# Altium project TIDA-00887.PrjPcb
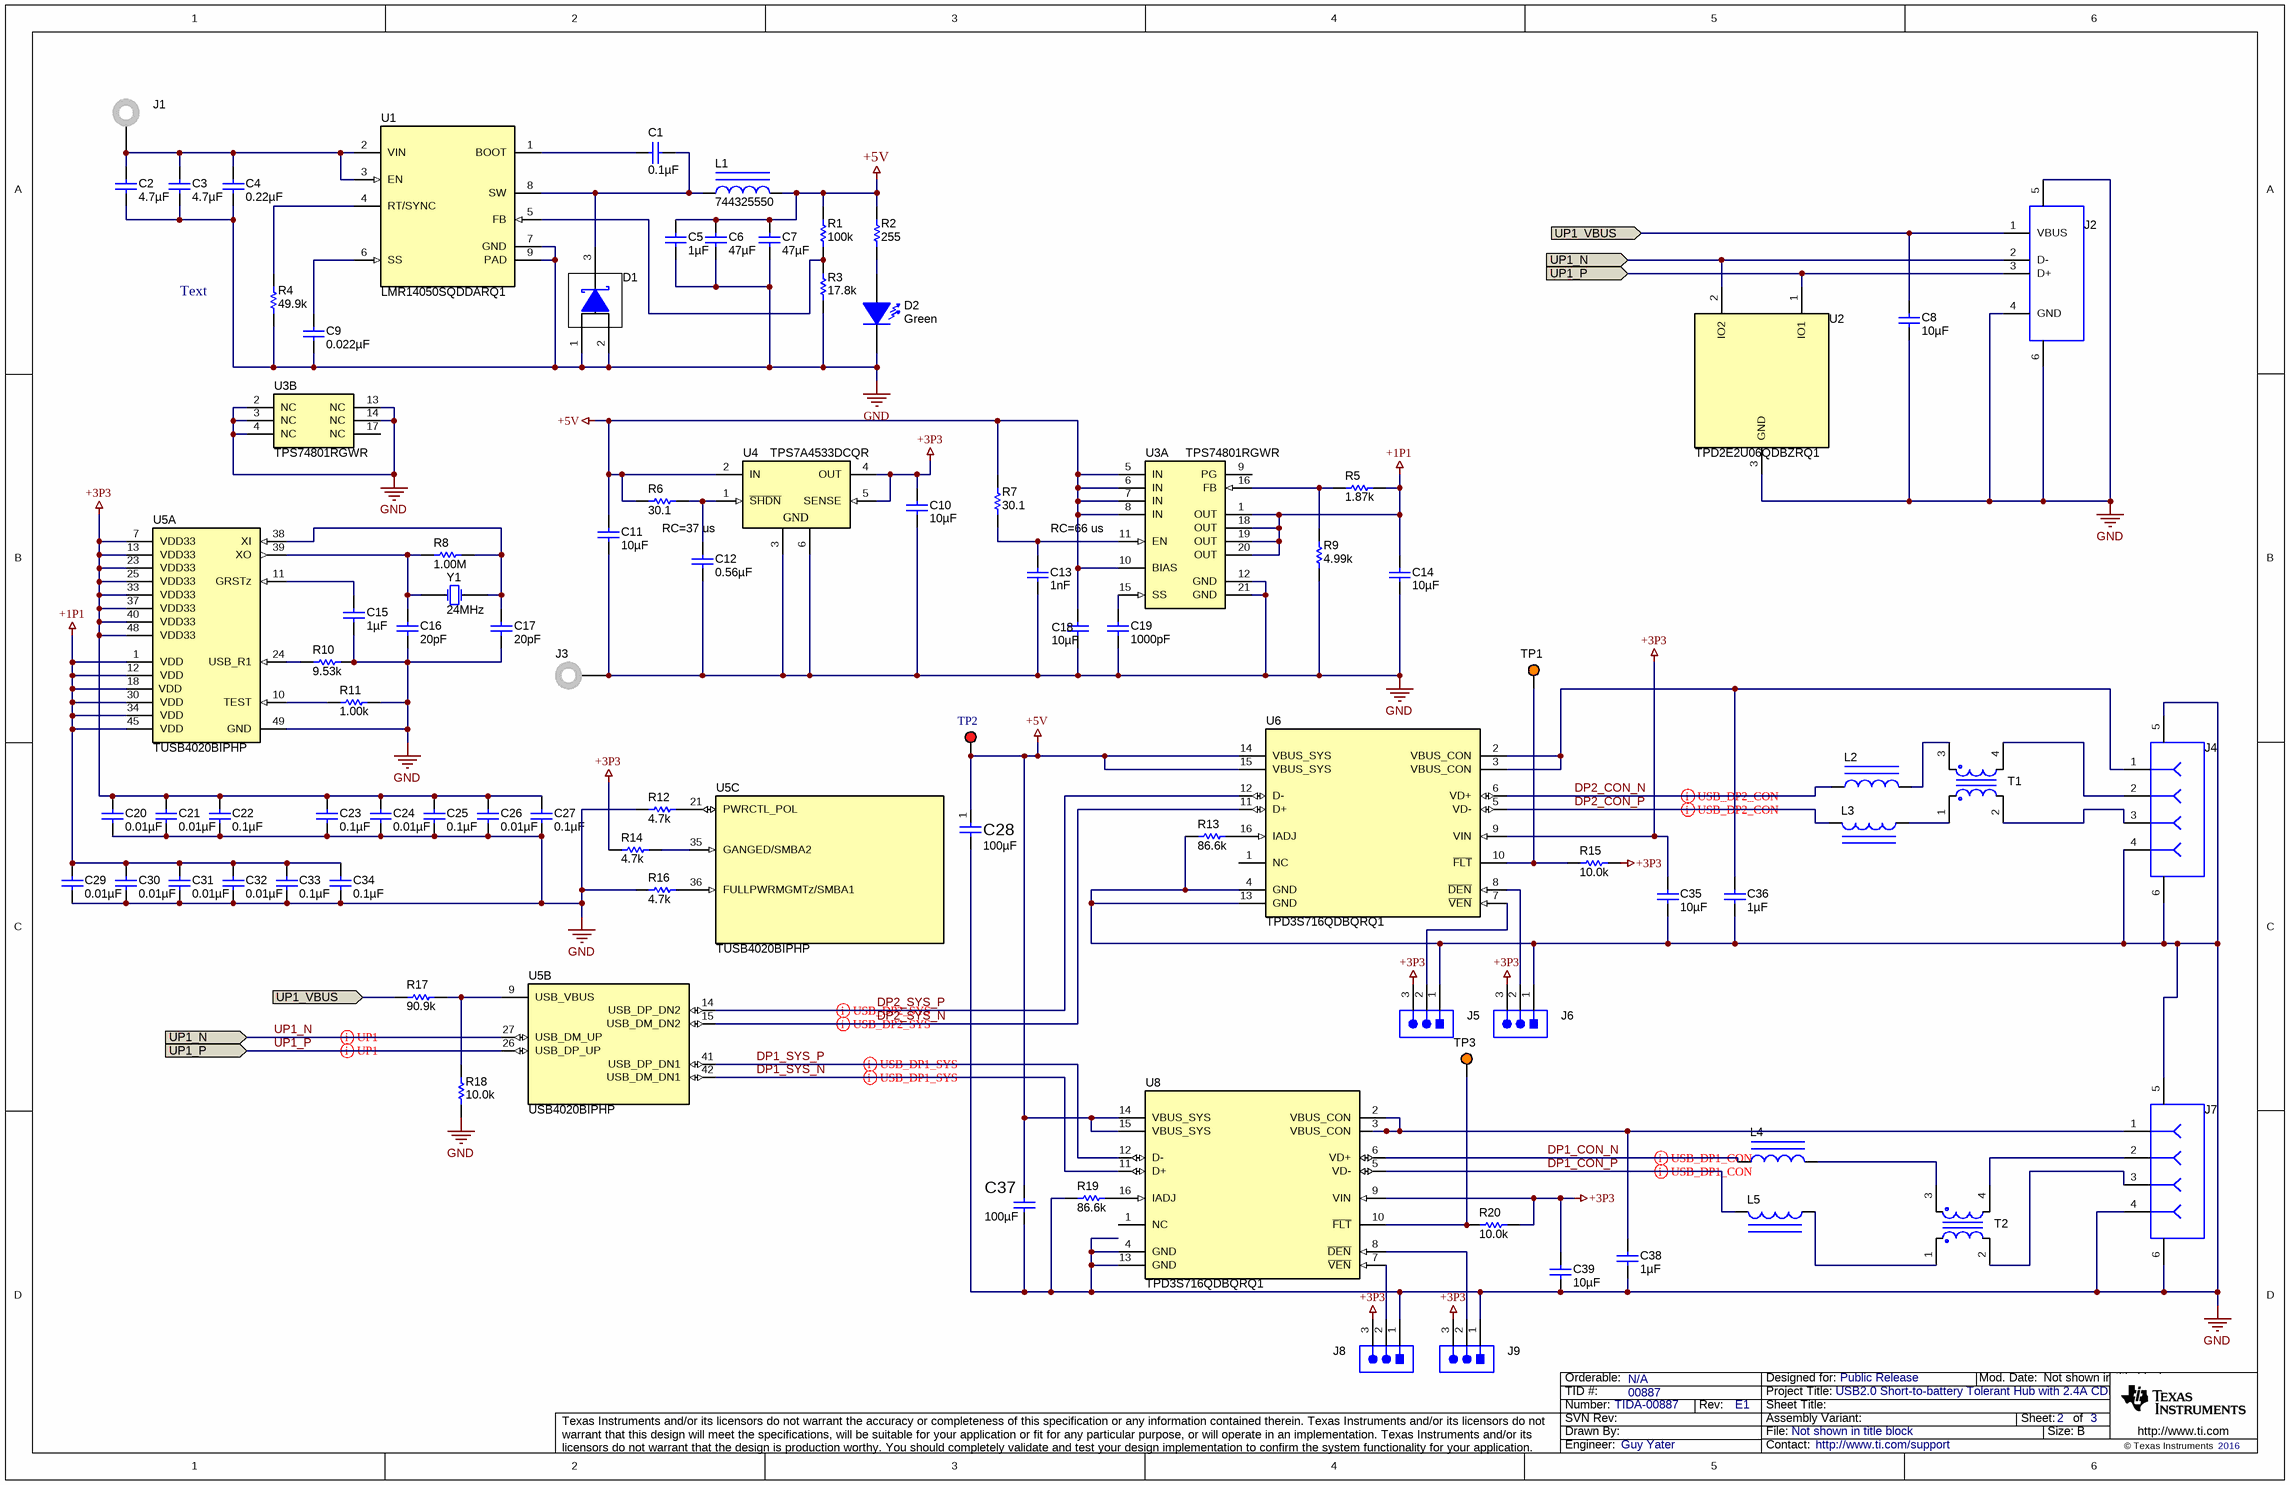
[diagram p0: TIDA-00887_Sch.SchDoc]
TID: 00887; TechSupport: http://www.ti.com/support; SCH_Rev: E1; PRJ_Title: USB2.0 Short-to-battery Tolerant Hub with 2.4A CDP + DCP support; PRJ_Number: TIDA-00887; PRJ_Engineer: Guy Yater; PRJ_Customer: Public Release; PCB_Rev: E1; PCB_Layout: Guy Yater; EVM_Orderable: N/A; CopyrightYear: 2016
2 sheets, 97 parts. Net scope: flat (ports and power ports of the same name join across sheets).
Board file: TIDA-00887_PCB.PcbDoc
Sheets:
  TIDA-00887_Sch.SchDoc
  TIDA-00887_Hardware.SchDoc

## Sheet TIDA-00887_Sch.SchDoc
size 431 x 279 mm; Date: Not shown in title block; ApprovedBy: Not shown in title block; CheckedBy: Not shown in title block; Author: Not shown in title block; CompanyName: Not shown in title block; Engineer: Not shown in title block; Organization: Not shown in title block; Address1: Not shown in title block; Address2: Not shown in title block; Address3: Not shown in title block; Address4: Not shown in title block; DocumentNumber: 1; Revision: Use project parameter SCH_Rev; SheetNumber: 2; SheetTotal: 3; PageSetup: Record=PageOptions¦CenterHorizontal=True¦CenterVertical=True¦PrintScale=1.00¦XCorrection=1.00¦YCorrection=1.00¦PrintKind=0¦BorderSize=5000000¦LeftOffset=0¦BottomOffset=0¦Orientation=2¦PaperLength=1000¦PaperWidth=1000¦Scale=100¦PaperSource=15¦PrintQuality=600¦MediaType=1¦DitherType=10¦PaperKind=Letter¦PrintScaleMode=1

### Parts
C1  ValueDisplayed: 0.1µF  [0603]  (hidden comment: GRM188R71C104KA01D)
C2  ValueDisplayed: 4.7µF  [1210]  (hidden comment: GRM32ER71H475KA88L)
C3  ValueDisplayed: 4.7µF  [1210]  (hidden comment: GRM32ER71H475KA88L)
C4  ValueDisplayed: 0.22µF  [0805_HV]  (hidden comment: GRM21BR71H224KA01L)
C5  ValueDisplayed: 1µF  [0805_HV]  (hidden comment: GRM21BR71E105KA99L)
C6  ValueDisplayed: 47µF  [1210]  (hidden comment: GRM32ER61C476ME15L)
C7  ValueDisplayed: 47µF  [1210]  (hidden comment: GRM32ER61C476ME15L)
C8  ValueDisplayed: 10µF  [0805L]  (hidden comment: C2012X7R0J106M125AB)
C9  ValueDisplayed: 0.022µF  [0402]  (hidden comment: GRM155R71C223KA01D)
C10  ValueDisplayed: 10µF  [0805_HV]  (hidden comment: 0805YD106MAT2A)
C11  ValueDisplayed: 10µF  [0805_HV]  (hidden comment: 0805YD106MAT2A)
C12  ValueDisplayed: 0.56µF  [1206]  (hidden comment: 12063C564KAT2A)
C13  ValueDisplayed: 1nF  [1206_190]  (hidden comment: 202R18W102KV4E)
C14  ValueDisplayed: 10µF  [0805_HV]  (hidden comment: 0805YD106MAT2A)
C15  ValueDisplayed: 1µF  [0402]  (hidden comment: GRM155R70J105MA12D)
C16  ValueDisplayed: 20pF  [0402]  (hidden comment: GRM1555C1H200JA01D)
C17  ValueDisplayed: 20pF  [0402]  (hidden comment: GRM1555C1H200JA01D)
C18  ValueDisplayed: 10µF  [0805_HV]  (hidden comment: 0805YD106MAT2A)
C19  ValueDisplayed: 1000pF  [1206_190]  (hidden comment: 202R18W102KV4E)
C20  ValueDisplayed: 0.01µF  [0402]  (hidden comment: GRM155R71H103KA88D)
C21  ValueDisplayed: 0.01µF  [0402]  (hidden comment: GRM155R71H103KA88D)
C22  ValueDisplayed: 0.1µF  [0402]  (hidden comment: TMK105B7104MV-FR)
C23  ValueDisplayed: 0.1µF  [0402]  (hidden comment: TMK105B7104MV-FR)
C24  ValueDisplayed: 0.01µF  [0402]  (hidden comment: GRM155R71H103KA88D)
C25  ValueDisplayed: 0.1µF  [0402]  (hidden comment: TMK105B7104MV-FR)
C26  ValueDisplayed: 0.01µF  [0402]  (hidden comment: GRM155R71H103KA88D)
C27  ValueDisplayed: 0.1µF  [0402]  (hidden comment: TMK105B7104MV-FR)
C28  ValueDisplayed: 100µF  [1210_280]  (hidden comment: C1210C107M8PACTU)
C29  ValueDisplayed: 0.01µF  [0402]  (hidden comment: GRM155R71H103KA88D)
C30  ValueDisplayed: 0.01µF  [0402]  (hidden comment: GRM155R71H103KA88D)
C31  ValueDisplayed: 0.01µF  [0402]  (hidden comment: GRM155R71H103KA88D)
C32  ValueDisplayed: 0.01µF  [0402]  (hidden comment: GRM155R71H103KA88D)
C33  ValueDisplayed: 0.1µF  [0402]  (hidden comment: TMK105B7104MV-FR)
C34  ValueDisplayed: 0.1µF  [0402]  (hidden comment: TMK105B7104MV-FR)
C35  ValueDisplayed: 10µF  [0805L]  (hidden comment: C2012X7R0J106M125AB)
C36  ValueDisplayed: 1µF  [1206_190]  (hidden comment: GCM31CR72A105KA03)
C37  ValueDisplayed: 100µF  [1210_280]  (hidden comment: C1210C107M8PACTU)
C38  ValueDisplayed: 1µF  [1206_190]  (hidden comment: GCM31CR72A105KA03)
C39  ValueDisplayed: 10µF  [0805L]  (hidden comment: C2012X7R0J106M125AB)
D1  PDS560-13  [PowerDI5]  (value not drawn)
D2  value Green  [LED_LTST-C171]  (hidden comment: LTST-C171GKT)
J1  575-4  [Keystone_575-4]  (value not drawn)
J2  67068-8000  [MOLEX_67068-8000]  (value not drawn)
J3  575-4  [Keystone_575-4]  (value not drawn)
J4  292303-4  [CONN_TE_292303-4]  (value not drawn)
J5  PEC03SAAN  [CONN_PEC03SAAN]  (value not drawn)
J6  PEC03SAAN  [CONN_PEC03SAAN]  (value not drawn)
J7  292303-4  [CONN_TE_292303-4]  (value not drawn)
J8  PEC03SAAN  [CONN_PEC03SAAN]  (value not drawn)
J9  PEC03SAAN  [CONN_PEC03SAAN]  (value not drawn)
L1  744325550  [WE-HC6]
L2  LQG15HS10NJ02D  [IND_LQG15H]  (value not drawn)
L3  LQG15HS10NJ02D  [IND_LQG15H]  (value not drawn)
L4  LQG15HS10NJ02D  [IND_LQG15H]  (value not drawn)
L5  LQG15HS10NJ02D  [IND_LQG15H]  (value not drawn)
R1  ValueDisplayed: 100k  [0402]  (hidden comment: CRCW0402100KDHEDP)
R2  ValueDisplayed: 255  [0402]  (hidden comment: CRCW0402255RFKED)
R3  ValueDisplayed: 17.8k  [0402]  (hidden comment: CRCW040217K8FKED)
R4  ValueDisplayed: 49.9k  [0402]  (hidden comment: CRCW040249K9FKED)
R5  ValueDisplayed: 1.87k  [0402]  (hidden comment: CRCW04021K87FKED)
R6  ValueDisplayed: 30.1  [0402]  (hidden comment: CRCW040230R1FKED)
R7  ValueDisplayed: 30.1  [0402]  (hidden comment: CRCW040230R1FKED)
R8  ValueDisplayed: 1.00M  [0402]  (hidden comment: CRCW04021M00FKED)
R9  ValueDisplayed: 4.99k  [0402]  (hidden comment: CRCW04024K99FKED)
R10  ValueDisplayed: 9.53k  [0402]  (hidden comment: CRCW04029K53FKED)
R11  ValueDisplayed: 1.00k  [0402]  (hidden comment: CRCW04021K00FKED)
R12  ValueDisplayed: 4.7k  [0402]  (hidden comment: CRCW04024K70JNED)
R13  ValueDisplayed: 86.6k  [0603]  (hidden comment: CRCW060386K6FKEA)
R14  ValueDisplayed: 4.7k  [0402]  (hidden comment: CRCW04024K70JNED)
R15  value 10.0k  [0603]  (hidden comment: CRCW060310K0FKEA)
R16  ValueDisplayed: 4.7k  [0402]  (hidden comment: CRCW04024K70JNED)
R17  ValueDisplayed: 90.9k  [0402]  (hidden comment: CRCW040290K9FKED)
R18  ValueDisplayed: 10.0k  [0402]  (hidden comment: CRCW040210K0DHEDP)
R19  ValueDisplayed: 86.6k  [0603]  (hidden comment: CRCW060386K6FKEA)
R20  value 10.0k  [0603]  (hidden comment: CRCW060310K0FKEA)
T1  mcf12102g900  [LCCI-44]  (value not drawn)
T2  mcf12102g900  [LCCI-44]  (value not drawn)
TP1  5008  [Keystone5008]  (value not drawn)
TP2  5000  [Keystone5000]  (value not drawn)
TP3  5008  [Keystone5008]  (value not drawn)
U1  LMR14050SQDDARQ1  [DDA0008E_N]
U2  TPD2E2U06QDBZRQ1  [DBZ0003A_N]
U3  TPS74801RGWR  [RGW0020A]  (parts A,B of 2)
U4  TPS7A4533DCQR  [DCQ0006A_N]
U5  TUSB4020BIPHP  [PHP0048C_N]  (parts A,B,C of 4)
U6  TPD3S716QDBQRQ1  [DBQ0016A_N]
U8  TPD3S716QDBQRQ1  [DBQ0016A_N]
Y1  Frequency: 24MHz  [445C25D24M00000]  (hidden comment: 445C25D24M00000)

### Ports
UP1_N, UP1_P, UP1_VBUS

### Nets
+1P1: C14.1 C29.2 C30.2 C31.2 C32.2 C33.2 C34.2 R5.2 U3.1(OUT) U3.18(OUT) U3.19(OUT) U3.20(OUT) U5.1(VDD) U5.12(VDD) U5.18(VDD) U5.30(VDD) U5.34(VDD) U5.45(VDD)
+3P3: C10.1 C20.2 C21.2 C22.2 C23.2 C24.2 C25.2 C26.2 C27.2 C35.1 C39.1 J5.3 J6.3 J8.3 J9.3 R14.1 R15.2 R20.2 U4.4(OUT) U4.5(SENSE) U5.7(VDD33) U5.13(VDD33) U5.23(VDD33) U5.25(VDD33) U5.33(VDD33) U5.37(VDD33) U5.40(VDD33) U5.48(VDD33) U6.9(VIN) U8.9(VIN)
+5V: C5.1 C6.1 C7.1 C11.1 C18.1 C28.1 C37.1 L1.2 R1.1 R2.1 R6.2 R7.2 TP2.1 U3.5(IN) U3.6(IN) U3.7(IN) U3.8(IN) U3.10(BIAS) U4.2(IN) U6.14(VBUS_SYS) U6.15(VBUS_SYS) U8.14(VBUS_SYS) U8.15(VBUS_SYS)
GND: C2.1 C3.1 C4.1 C5.2 C6.2 C7.2 C8.2 C9.1 C10.2 C11.2 C12.1 C13.1 C14.2 C15.1 C16.2 C17.2 C18.2 C19.1 C20.1 C21.1 C22.1 C23.1 C24.1 C25.1 C26.1 C27.1 C28.2 C29.1 C30.1 C31.1 C32.1 C33.1 C34.1 C35.2 C36.2 C37.2 C38.2 C39.2 D1.1(A) D1.2(A) D2.2(K) J2.4(GND) J2.5(Shield) J2.6(Shield) J3.1 J4.4 J4.5 J4.6 J5.1 J6.1 J7.4 J7.5 J7.6 J8.1 J9.1 R3.2 R4.2 R9.1 R10.2 R11.2 R12.1 R13.1 R16.1 R18.1 R19.1 U1.7(GND) U1.9(PAD) U2.3(GND) U3.2(NC) U3.3(NC) U3.4(NC) U3.12(GND) U3.13(NC) U3.14(NC) U3.21(GND) U4.3(GND) U4.6(GND) U5.49(GND) U6.4(GND) U6.13(GND) U8.4(GND) U8.13(GND)
DP1_CON_N: L4.1 U8.6(VD+)
DP1_CON_P: L5.1 U8.5(VD-)
DP1_SYS_N: U5.42(USB_DM_DN1) U8.11(D+)
DP1_SYS_P: U5.41(USB_DP_DN1) U8.12(D-)
DP2_CON_N: L2.1 U6.6(VD+)
DP2_CON_P: L3.1 U6.5(VD-)
DP2_SYS_N: U5.15(USB_DM_DN2) U6.11(D+)
DP2_SYS_P: U5.14(USB_DP_DN2) U6.12(D-)
UP1_N: J2.2(D-) U2.2(IO2) U5.27(USB_DM_UP) ; port UP1_N
UP1_P: J2.3(D+) U2.1(IO1) U5.26(USB_DP_UP) ; port UP1_P
UP1_VBUS: C8.1 J2.1(VBUS) R17.1 ; port UP1_VBUS
NetC1_1: C1.1 D1.3(K) L1.1 U1.8(SW)
NetC1_2: C1.2 U1.1(BOOT)
NetC2_2: C2.2 C3.2 C4.2 J1.1 U1.2(VIN) U1.3(EN)
NetC9_2: C9.2 U1.6(SS)
NetC12_2: C12.2 R6.1 U4.1(~{SHDN})
NetC13_2: C13.2 R7.1 U3.11(EN)
NetC15_2: C15.2 U5.11(GRSTz)
NetC16_1: C16.1 R8.1 U5.39(XO) Y1.1(OSC1)
NetC17_1: C17.1 R8.2 U5.38(XI) Y1.2(OSC2)
NetC19_2: C19.2 U3.15(SS)
NetC36_1: C36.1 J4.1 U6.2(VBUS_CON) U6.3(VBUS_CON)
NetC38_1: C38.1 J7.1 U8.2(VBUS_CON) U8.3(VBUS_CON)
NetD2_1: D2.1(A) R2.2
NetJ4_2: J4.2 T1.4
NetJ4_3: J4.3 T1.2
NetJ5_2: J5.2 U6.7(~{VEN})
NetJ6_2: J6.2 U6.8(~{DEN})
NetJ7_2: J7.2 T2.4
NetJ7_3: J7.3 T2.2
NetJ8_2: J8.2 U8.7(~{VEN})
NetJ9_2: J9.2 U8.8(~{DEN})
NetL2_2: L2.2 T1.3
NetL3_2: L3.2 T1.1
NetL4_2: L4.2 T2.3
NetL5_2: L5.2 T2.1
NetR1_2: R1.2 R3.1 U1.5(FB)
NetR4_1: R4.1 U1.4(RT/SYNC)
NetR5_1: R5.1 R9.2 U3.16(FB)
NetR10_1: R10.1 U5.24(USB_R1)
NetR11_1: R11.1 U5.10(TEST)
NetR12_2: R12.2 U5.21(PWRCTL_POL)
NetR13_2: R13.2 U6.16(IADJ)
NetR14_2: R14.2 U5.35(GANGED/SMBA2)
NetR15_1: R15.1 TP1.1 U6.10(~{FLT})
NetR16_2: R16.2 U5.36(FULLPWRMGMTz/SMBA1)
NetR17_2: R17.2 R18.2 U5.9(USB_VBUS)
NetR19_2: R19.2 U8.16(IADJ)
NetR20_1: R20.1 TP3.1 U8.10(~{FLT})

Not connected (* = marked no-connect by the designer): U3 9(PG) 17(NC); U6 1(NC); U8 1(NC)

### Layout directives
differential pair: DP1_CON_N, DP1_CON_P, DP1_SYS_N, DP1_SYS_P, DP2_CON_N, DP2_CON_P, DP2_SYS_N, DP2_SYS_P, UP1_N, UP1_P

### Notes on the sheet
- Text
- RC=37 us
- RC=66 us

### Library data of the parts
C1 = GRM188R71C104KA01D: CAP, CERM, 0.1 µF, 16 V, +/- 10%, X7R, 0603; Manufacturer: MuRata; Polarized: N; CompType: Capacitor; Value: 0.1uF; U/M: EA; Cap_F: 0.0000001; Tolerance_%: 10; Value1: Unknown; VDC_V: 16; Value2: 16V; TaMin_C: -55; TaMax_C: 125; AEC Category: Q200
C2 C3 = GRM32ER71H475KA88L: CAP, CERM, 4.7 µF, 50 V, +/- 10%, X7R, 1210; Manufacturer: MuRata; Polarized: N; CompType: Capacitor; Value: 4.7uF; U/M: EA; Cap_F: 0.0000047; Tolerance_%: 10; ESR_ohm: 0.002; Value1: 0.002 ohm; VDC_V: 50; Value2: 50V; TaMin_C: -55; TaMax_C: 125; AEC Category: Q200
C4 = GRM21BR71H224KA01L: CAP, CERM, 0.22 µF, 50 V, +/- 10%, X7R, 0805; Manufacturer: MuRata; Polarized: N; CompType: Capacitor; Value: 0.22uF; U/M: EA; Cap_F: 0.00000022; Tolerance_%: 10; Value1: Unknown; VDC_V: 50; Value2: 50V; TaMin_C: -55; TaMax_C: 125; Cap_Case: 0805; AEC Category: Q200
C5 = GRM21BR71E105KA99L: CAP, CERM, 1 µF, 25 V, +/- 10%, X7R, 0805; Manufacturer: MuRata; Polarized: N; CompType: Capacitor; Value: 1uF; U/M: EA; Cap_F: 0.000001; Tolerance_%: 10; Value1: Unknown; VDC_V: 25; Value2: 25V; TaMin_C: -55; TaMax_C: 125; Cap_Case: 0805; AEC Category: Q200
C6 C7 = GRM32ER61C476ME15L: CAP, CERM, 47 µF, 16 V, +/- 20%, X5R, 1210; Manufacturer: MuRata; Polarized: N; CompType: Capacitor; Value: 47uF; U/M: EA; Cap_F: 0.000047; Tolerance_%: 20; ESR_ohm: 0.002; Value1: 0.002 ohm; VDC_V: 16; Value2: 16V; TaMin_C: -55; TaMax_C: 85; AEC Category: Q200
C8 C35 C39 = C2012X7R0J106M125AB: CAP, CERM, 10 µF, 6.3 V, +/- 20%, X7R, 0805; Manufacturer: TDK; Polarized: N; CompType: Capacitor; Value: 10uF; U/M: EA; Cap_F: 0.00001; Tolerance_%: 20; Value1: Unknown; VDC_V: 6.3; Value2: 6.3V; TaMin_C: -55; TaMax_C: 125; Cap_Case: 0805
C9 = GRM155R71C223KA01D: CAP, CERM, 0.022 µF, 16 V, +/- 10%, X7R, 0402; Manufacturer: MuRata; Polarized: N; CompType: Capacitor; Value: 0.022uF; U/M: EA; Cap_F: 0.000000022; Tolerance_%: 10; Value1: Unknown; VDC_V: 16; Value2: 16V; TaMin_C: -55; TaMax_C: 125; AEC Category: Q200
C10 C11 C14 C18 = 0805YD106MAT2A: CAP, CERM, 10 µF, 16 V, +/- 20%, X5R, 0805; Manufacturer: AVX; Polarized: N; CompType: Capacitor; Value: 10uF; U/M: EA; Cap_F: 0.00001; Tolerance_%: 20; Value1: Unknown; VDC_V: 16; Value2: 16V; TaMin_C: -55; TaMax_C: 85; Cap_Case: 0805; AEC Category: Q200
C12 = 12063C564KAT2A: CAP, CERM, 0.56 µF, 25 V, +/- 10%, X7R, 1206; Manufacturer: AVX; Polarized: N; CompType: Capacitor; Value: 0.56uF; U/M: EA; Cap_F: 0.00000056; Tolerance_%: 10; ESR_ohm: 0.017; Value1: 0.017 ohm; VDC_V: 25; Value2: 25V; TaMin_C: -55; TaMax_C: 125; AEC Category: Q200
C13 C19 = 202R18W102KV4E: CAP, CERM, 1000 pF, 2000 V, +/- 10%, X7R, 1206_190; Manufacturer: Johanson Technology; Polarized: N; CompType: Capacitor; Value: 1000pF; U/M: EA; Cap_F: 0.000000001; Tolerance_%: 10; Value1: Unknown; VDC_V: 2000; Value2: 2000V; TaMin_C: -55; TaMax_C: 125; Cap_Case: 1206; AEC Category: Q200
C15 = GRM155R70J105MA12D: CAP, CERM, 1 µF, 6.3 V, +/- 20%, X7R, 0402; Manufacturer: MuRata; Polarized: N; CompType: Capacitor; Value: 1uF; U/M: EA; Cap_F: 0.000001; Tolerance_%: 20; Value1: Unknown; VDC_V: 6.3; Value2: 6.3V; TaMin_C: -55; TaMax_C: 125; AEC Category: Q200
C16 C17 = GRM1555C1H200JA01D: CAP, CERM, 20 pF, 50 V, +/- 5%, C0G/NP0, 0402; Manufacturer: MuRata; Polarized: N; CompType: Capacitor; Value: 20pF; U/M: EA; Cap_F: 0.00000000002; Tolerance_%: 5; Value1: Unknown; VDC_V: 50; Value2: 50V; TaMin_C: -55; TaMax_C: 125; AEC Category: Q200
C20 C21 C24 C26 C29-C32 = GRM155R71H103KA88D: CAP, CERM, 0.01 µF, 50 V, +/- 10%, X7R, 0402; Manufacturer: MuRata; Polarized: N; CompType: Capacitor; Value: 0.01uF; U/M: EA; Cap_F: 0.00000001; Tolerance_%: 10; Value1: Unknown; VDC_V: 50; Value2: 50V; TaMin_C: -55; TaMax_C: 125; AEC Category: Q200
C22 C23 C25 C27 C33 C34 = TMK105B7104MV-FR: CAP, CERM, 0.1 µF, 25 V, +/- 20%, X7R, 0402; Manufacturer: Taiyo Yuden; Polarized: N; CompType: Capacitor; Value: 0.1uF; U/M: EA; Cap_F: 0.0000001; Tolerance_%: 20; Value1: Unknown; VDC_V: 25; Value2: 25V; TaMin_C: -55; TaMax_C: 125; AEC Category: Q200
C28 C37 = C1210C107M8PACTU: CAP, CERM, 100 µF, 10 V, +/- 20%, X5R, 1210; Manufacturer: Wurth Elektronik; Polarized: N; CompType: Capacitor; Value: 100uF; U/M: EA; Cap_F: 0.0001; Tolerance_%: 20; Value1: Unknown; VDC_V: 10; Value2: 10V; TaMin_C: -55; TaMax_C: 85; Cap_Case: 1210
C36 C38 = GCM31CR72A105KA03: CAP, CERM, 1 µF, 100 V, +/- 10%, X7R, AEC-Q200 Grade 1, 1206_190; Manufacturer: MuRata; Polarized: N; CompType: Capacitor; Value: 1uF; U/M: EA; Cap_F: 0.000001; Tolerance_%: 10; Value1: Unknown; VDC_V: 100; Value2: 100V; TaMin_C: -55; TaMax_C: 125; Cap_Case: 1206; AEC Category: Q200; AEC Qualified: Y; AEC Grade: 1
D1 = PDS560-13: Diode, Schottky, 60 V, 5 A, PowerDI5; Manufacturer: Diodes Inc.; U/M: EA; Vf_V: 0.67; Value: 60V; Value1: 5A; Value2: 0.67V; Io_A: 5; Vr_V: 60; TJmax_C: 150; AEC Category: Q101
D2 = LTST-C171GKT: LED, Green, SMD; Manufacturer: Lite-On; Type: AlInGaP; Vf_V: 2.1; Value2: 2.1V; Io_A: 20; Value1: W; U/M: EA
J1 J3 = 575-4: Standard Banana Jack, Uninsulated, 5.5mm; Manufacturer: Keystone; CompType: Connector; U/M: EA
J2 = 67068-8000: Connector, Receptacle, USB TYPE B, R/A, Top Mount TH; Manufacturer: Molex; SymbolCreator: a0412235; U/M: EA
J4 J7 = 292303-4: Connector, Receptacle, USB Type A, R/A, Top Mount TH; Manufacturer: TE Connectivity; SymbolCreator: a0412235; U/M: EA
J5 J6 J8 J9 = PEC03SAAN: Header, 100mil, 3x1, Tin, TH; Manufacturer: Sullins Connector Solutions; SymbolCreator: a0799628; Pitch_mm: 2.54; Gender: Male; Shrouded: N; Row_Count: 1; Current_A: 3; Voltage_V: 1800; Cert_UL: Y
L1 = 744325550: Inductor, Shielded Drum Core, Superflux, 5.5 µH, 10 A, 0.0112 ohm, SMD; Manufacturer: Wurth Elektronik eiSos; Value: 5.5uH; ValueDisplayed: 5.5µH; Ind_H: 5.5E-6; Imax_A: 10; Irms: 10A @ 50C rise; Isat: 12A @ 30% inductance drop; DCR_ohm: 0.0112; Value2: 10A
L2-L5 = LQG15HS10NJ02D: Inductor, Multilayer, Air Core, 10nH, 0.3A, 0.26 ohm, SMD; Manufacturer: MuRata; Ind_H: 10.0E-9; Imax_A: 0.3; Irms: 0.3A @ C rise; Isat: 0.3A @ % inductance drop; DCR_ohm: 0.26
R1 = CRCW0402100KDHEDP: RES, 100 k, 0.5%, 0.063 W, 0402; Manufacturer: Vishay-Dale; CompType: Resistor; Value: 100k; Res_ohm: 100000; Tolerance_%: 0.5; Power_W: 0.063; Value2: 0.063W; VDC_V: 50; TempCo: 50 ppm/C; EIA_Code: E192; U/M: EA; AEC Category: Q200
R2 = CRCW0402255RFKED: RES, 255, 1%, 0.063 W, 0402; Manufacturer: Vishay-Dale; CompType: Resistor; Value: 255; Value_Code: 255R; Tolerance_%: 1; Power_W: 0.063; Value2: 0.063W; VDC_V: 50; TempCo: 100 ppm/C; EIA_Code: E96; U/M: EA; AEC Category: Q200
R3 = CRCW040217K8FKED: RES, 17.8 k, 1%, 0.063 W, 0402; Manufacturer: Vishay-Dale; CompType: Resistor; Value: 17.8k; Res_ohm: 17800; Value_Code: 17k8; Tolerance_%: 1; Power_W: 0.063; Value2: 0.063W; VDC_V: 50; TempCo: 100 ppm/C; EIA_Code: E96; U/M: EA; AEC Category: Q200
R4 = CRCW040249K9FKED: RES, 49.9 k, 1%, 0.063 W, 0402; Manufacturer: Vishay-Dale; CompType: Resistor; Value: 49.9k; Res_ohm: 49900; Value_Code: 49k9; Tolerance_%: 1; Power_W: 0.063; Value2: 0.063W; VDC_V: 50; TempCo: 100 ppm/C; EIA_Code: E96; U/M: EA; AEC Category: Q200
R5 = CRCW04021K87FKED: RES, 1.87 k, 1%, 0.063 W, 0402; Manufacturer: Vishay-Dale; CompType: Resistor; Value: 1.87k; Res_ohm: 1870; Value_Code: 1k87; Tolerance_%: 1; Power_W: 0.063; Value2: 0.063W; VDC_V: 50; TempCo: 100 ppm/C; EIA_Code: E96; U/M: EA; AEC Category: Q200
R6 R7 = CRCW040230R1FKED: RES, 30.1, 1%, 0.063 W, 0402; Manufacturer: Vishay-Dale; CompType: Resistor; Value: 30.1; Value_Code: 30R1; Tolerance_%: 1; Power_W: 0.063; Value2: 0.063W; VDC_V: 50; TempCo: 100 ppm/C; EIA_Code: E96; U/M: EA; AEC Category: Q200
R8 = CRCW04021M00FKED: RES, 1.00 M, 1%, 0.063 W, 0402; Manufacturer: Vishay-Dale; CompType: Resistor; Value: 1.00Meg; Res_ohm: 1000000; Value_Code: 1M00; Tolerance_%: 1; Power_W: 0.063; Value2: 0.063W; VDC_V: 50; TempCo: 100 ppm/C; EIA_Code: E96; U/M: EA; AEC Category: Q200
R9 = CRCW04024K99FKED: RES, 4.99 k, 1%, 0.063 W, 0402; Manufacturer: Vishay-Dale; CompType: Resistor; Value: 4.99k; Res_ohm: 4990; Value_Code: 4k99; Tolerance_%: 1; Power_W: 0.063; Value2: 0.063W; VDC_V: 50; TempCo: 100 ppm/C; EIA_Code: E96; U/M: EA; AEC Category: Q200
R10 = CRCW04029K53FKED: RES, 9.53 k, 1%, 0.063 W, 0402; Manufacturer: Vishay-Dale; CompType: Resistor; Value: 9.53k; Res_ohm: 9530; Value_Code: 9k53; Tolerance_%: 1; Power_W: 0.063; Value2: 0.063W; VDC_V: 50; TempCo: 100 ppm/C; EIA_Code: E96; U/M: EA; AEC Category: Q200
R11 = CRCW04021K00FKED: RES, 1.00 k, 1%, 0.063 W, 0402; Manufacturer: Vishay-Dale; CompType: Resistor; Value: 1.00k; Res_ohm: 1000; Value_Code: 1k00; Tolerance_%: 1; Power_W: 0.063; Value2: 0.063W; VDC_V: 50; TempCo: 100 ppm/C; EIA_Code: E96; U/M: EA; AEC Category: Q200
R12 R14 R16 = CRCW04024K70JNED: RES, 4.7 k, 5%, 0.063 W, 0402; Manufacturer: Vishay-Dale; CompType: Resistor; Value: 4.7k; Res_ohm: 4700; Value_Code: 4k70; Tolerance_%: 5; Power_W: 0.063; Value2: 0.063W; VDC_V: 50; TempCo: 200 ppm/C; EIA_Code: E24; U/M: EA; AEC Category: Q200
R13 R19 = CRCW060386K6FKEA: RES, 86.6 k, 1%, 0.1 W, 0603; Manufacturer: Vishay-Dale; CompType: Resistor; Value: 86.6k; Res_ohm: 86600; Value_Code: 86k6; Tolerance_%: 1; Power_W: 0.1; Value2: 0.1W; VDC_V: 75; TempCo: 100 ppm/C; EIA_Code: E96; U/M: EA; AEC Category: Q200
R15 R20 = CRCW060310K0FKEA: RES, 10.0k ohm, 1%, 0.1W, 0603; Manufacturer: Vishay-Dale; CompType: Resistor; Res_ohm: 10000; Value_Code: 10k0; Tolerance_%: 1; Power_W: 0.1; VDC_V: 75; TempCo: 100 ppm/C; EIA_Code: E96; U/M: EA
R17 = CRCW040290K9FKED: RES, 90.9 k, 1%, 0.063 W, 0402; Manufacturer: Vishay-Dale; CompType: Resistor; Value: 90.9k; Res_ohm: 90900; Value_Code: 90k9; Tolerance_%: 1; Power_W: 0.063; Value2: 0.063W; VDC_V: 50; TempCo: 100 ppm/C; EIA_Code: E96; U/M: EA; AEC Category: Q200
R18 = CRCW040210K0DHEDP: RES, 10.0 k, 0.5%, 0.063 W, 0402; Manufacturer: Vishay-Dale; CompType: Resistor; Value: 10.0k; Res_ohm: 10000; Value_Code: 10k0; Tolerance_%: 0.5; Power_W: 0.063; Value2: 0.063W; VDC_V: 50; TempCo: 50 ppm/C; EIA_Code: E192; U/M: EA; AEC Category: Q200
T1 T2 = PA2750NL: SMT Common Mode Choke; Manufacturer: Taiyo Yuden; Alternate Manufacturer: None; U/M: EA
TP1 TP3 = 5008: Test Point, Compact, Orange, TH; Manufacturer: Keystone; CompType: Test Point Loop; U/M: EA
TP2 = 5000: Test Point, Miniature, Red, TH; Manufacturer: Keystone; CompType: Test Point Loop; ContactFinish: Silver
U1 = LMR14050SQDDARQ1: SIMPLE SWITCHER 40 V 5 A, 2.2 MHz Step-Down Converter with 40 uA IQ, DDA0008E; Manufacturer: Texas Instruments; SymbolCreator: Altium; SizeArea_mm2: 31; SizeAreaWB_mm2: 57.4; SizeX_mm: 5; SizeY_mm: 6.2; SizeZ_mm: 1.7; CompType: IC; U/M: EA
U2 = TPD2E2U06QDBZRQ1: Dual-Channel High-Speed ESD Protectiong Device, DBZ0003A; Manufacturer: Texas Instruments; SymbolCreator: Altium; SizeArea_mm2: 7.5; SizeAreaWB_mm2: 14; SizeX_mm: 2.5; SizeY_mm: 3; SizeZ_mm: 1.12; CompType: IC; U/M: EA
U3 = TPS74801RGWR: Single Output LDO, 1.5 A, Adjustable 0.8 to 3.6 V Output, 0.8 to 5.5 V Input, with Programmable Soft Start, 20-pin VQFN (RGW), -40 to 125 degC, Green (RoHS & no Sb/Br); Manufacturer: Texas Instruments; Alternate PartNumber: Equivalent; Accuracy(%): 2; Iout(Max)(A): 1.5; Iq(Typ)(mA): 1; Power Good: TRUE; Rating: Catalog; SubFamily: Single Channel LDO; Vdo(Typ)(mV): 60; Vin(Max)(V): 5.5; Vin(Min)(V): 0.8; Vout Adj(Max)(V): 3.6
U4 = TPS7A4533DCQR: Single Output Fast Transient Response LDO, 1.5 A, Fixed 3.3 V Output, 2.1 to 20 V Input, 6-pin SOT-223 (DCQ), -40 to 125 degC, Green (RoHS & no Sb/Br); Manufacturer: Texas Instruments; Alternate PartNumber: Equivalent; Accuracy(%): 1; Fixed Output Options(V): 3.3; Iout(Max)(A): 1.5; SubFamily: Single Channel LDO; Vdo(Typ)(mV): 300; Vin(Max)(V): 20; Vin(Min)(V): 2.1
U5 = TSB41AB1PHPG4: 400 Mbps IEEE 1394a One-Port Cable Transceiver / Arbiter, 3.3V, 0 to 70 degC, 48-Pin HTQFP (PHP), Green (RoHS & no Sb/Br); Manufacturer: Texas Instruments; Alternate PartNumber: Equivalent; SubFamily: 1394 Physical Layer Controller; Speed(Max)(Mbps): 400; Ports: 1; Supply Voltage(s)(V): 3.3; 1394: True; Rating: Catalog
U6 U8 = TPD3S716QDBQRQ1: AUTOMOTIVE USB 2.0 Interface Protection with Short-to-Battery, Short-to-Ground Protection, and Adjustable Current Limit, DBQ0016A; Manufacturer: Texas Instruments; SymbolCreator: Altium; CompType: IC; U/M: EA
Y1 = ECS-240-20-5PX-TR: Crystal, 24.000MHz, 20pF, SMD; Manufacturer: CTS Freq Controls; SymbolCreator: a0412235; U/M: EA; TaMin_C: -10; TaMax_C: 70; Frequency Stability: ±50ppm

## Sheet TIDA-00887_Hardware.SchDoc
size 431 x 279 mm; Date: Not shown in title block; ApprovedBy: Not shown in title block; CheckedBy: Not shown in title block; Author: Not shown in title block; CompanyName: Not shown in title block; Engineer: Not shown in title block; Organization: Not shown in title block; Address1: Not shown in title block; Address2: Not shown in title block; Address3: Not shown in title block; Address4: Not shown in title block; DocumentNumber: 1; Revision: Use project parameter SCH_Rev; SheetNumber: 3; SheetTotal: 3; PageSetup: Record=PageOptions¦CenterHorizontal=True¦CenterVertical=True¦PrintScale=1.00¦XCorrection=1.00¦YCorrection=1.00¦PrintKind=0¦BorderSize=5000000¦LeftOffset=0¦BottomOffset=0¦Orientation=2¦PaperLength=1000¦PaperWidth=1000¦Scale=100¦PaperSource=15¦PrintQuality=600¦MediaType=1¦DitherType=10¦PaperKind=Letter¦PrintScaleMode=1
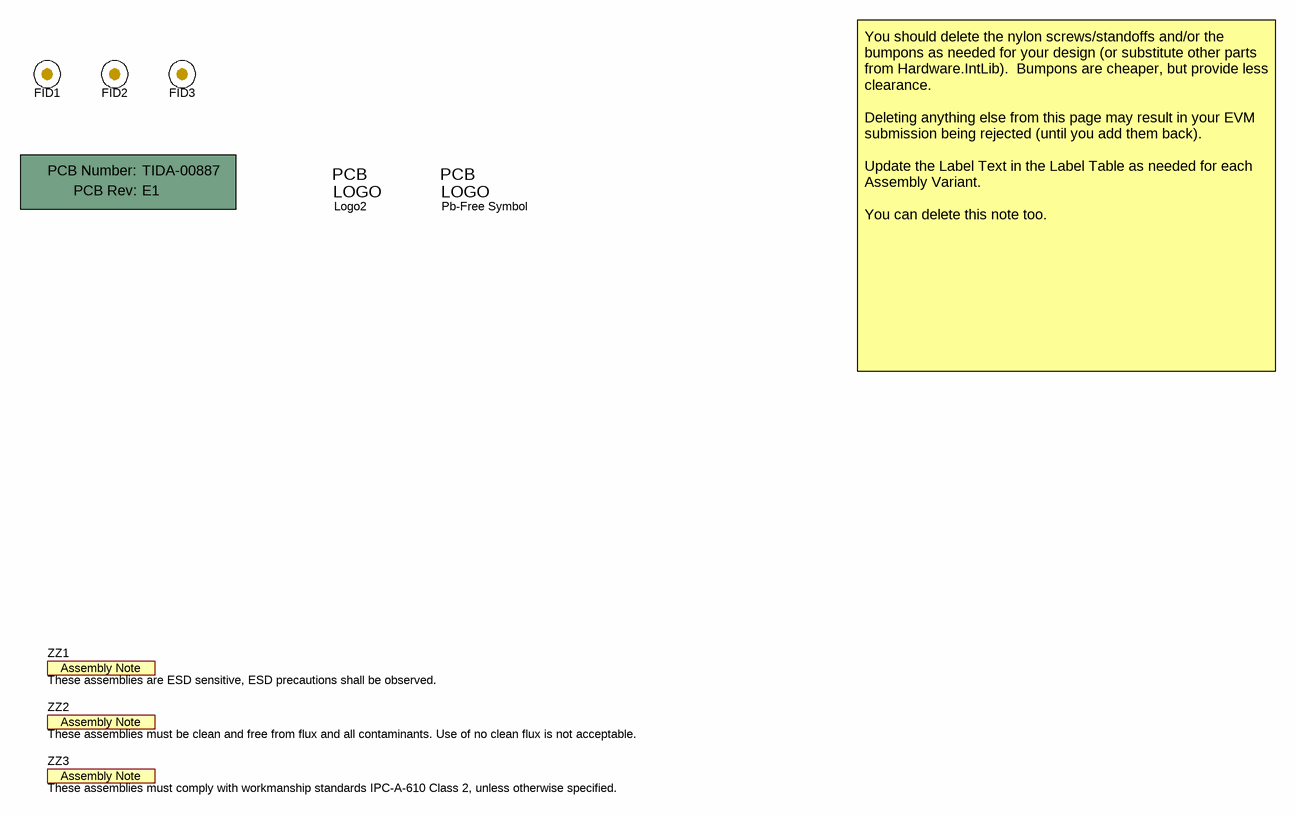
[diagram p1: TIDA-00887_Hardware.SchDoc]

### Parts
!PCB1  Printed Circuit Board  (value not drawn)  (mechanical)
FID1  Fiducial  [Fiducial10-20]  (value not drawn)
FID2  Fiducial  [Fiducial10-20]  (value not drawn)
FID3  Fiducial  [Fiducial10-20]  (value not drawn)
Logo1  Pb-Free Symbol  [Pb-Free_Overlay_Small]  (no BOM)
Logo2  Texas Instruments  [TI_Stacked_Overlay_Medium]  (value not drawn)  (no BOM)
ZZ1  These assemblies are ESD sensitive, ESD precautions shall be observed.  [AssemblyNote]  (no BOM)
ZZ2  These assemblies must be clean and free from flux and all contaminants. Use of no clean flux is not acceptable.  [AssemblyNote]  (no BOM)
ZZ3  These assemblies must comply with workmanship standards IPC-A-610 Class 2, unless otherwise specified.  [AssemblyNote]  (no BOM)

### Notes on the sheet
- You should delete the nylon screws/standoffs and/or the bumpons as needed for your design (or substitute other parts from Hardware.IntLib).  Bumpons are cheaper, but provide less clearance.
  Deleting anything else from this page may result in your EVM submission being rejected (until you add them back).
  Update the Label Text in the Label Table as needed for each Assembly Variant.
  You can delete this note too.

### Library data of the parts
!PCB1 = PCB: Manufacturer: Any; PartNumber: TIDA-00887; SymbolCreator: a0412235
FID1-FID3 = Fiducial: Fiducial mark.  There is nothing to buy or mount.; SymbolCreator: codlsc
Logo1 = Pb-Free: SymbolCreator: a0412235
Logo2 = TI_Logo: Texas Instrument Corporate Signature; SymbolCreator: a0412235
ZZ1-ZZ3 = AssemblyNote: SymbolCreator: codlsc

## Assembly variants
001: not fitted FID1 FID2 FID3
